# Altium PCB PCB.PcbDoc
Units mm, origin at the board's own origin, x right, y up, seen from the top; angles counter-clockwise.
Board outline 100 x 60 mm, 2 copper layers (Top Layer, Bottom Layer); 16 components, 14 nets, 66 pads, 0 vias.
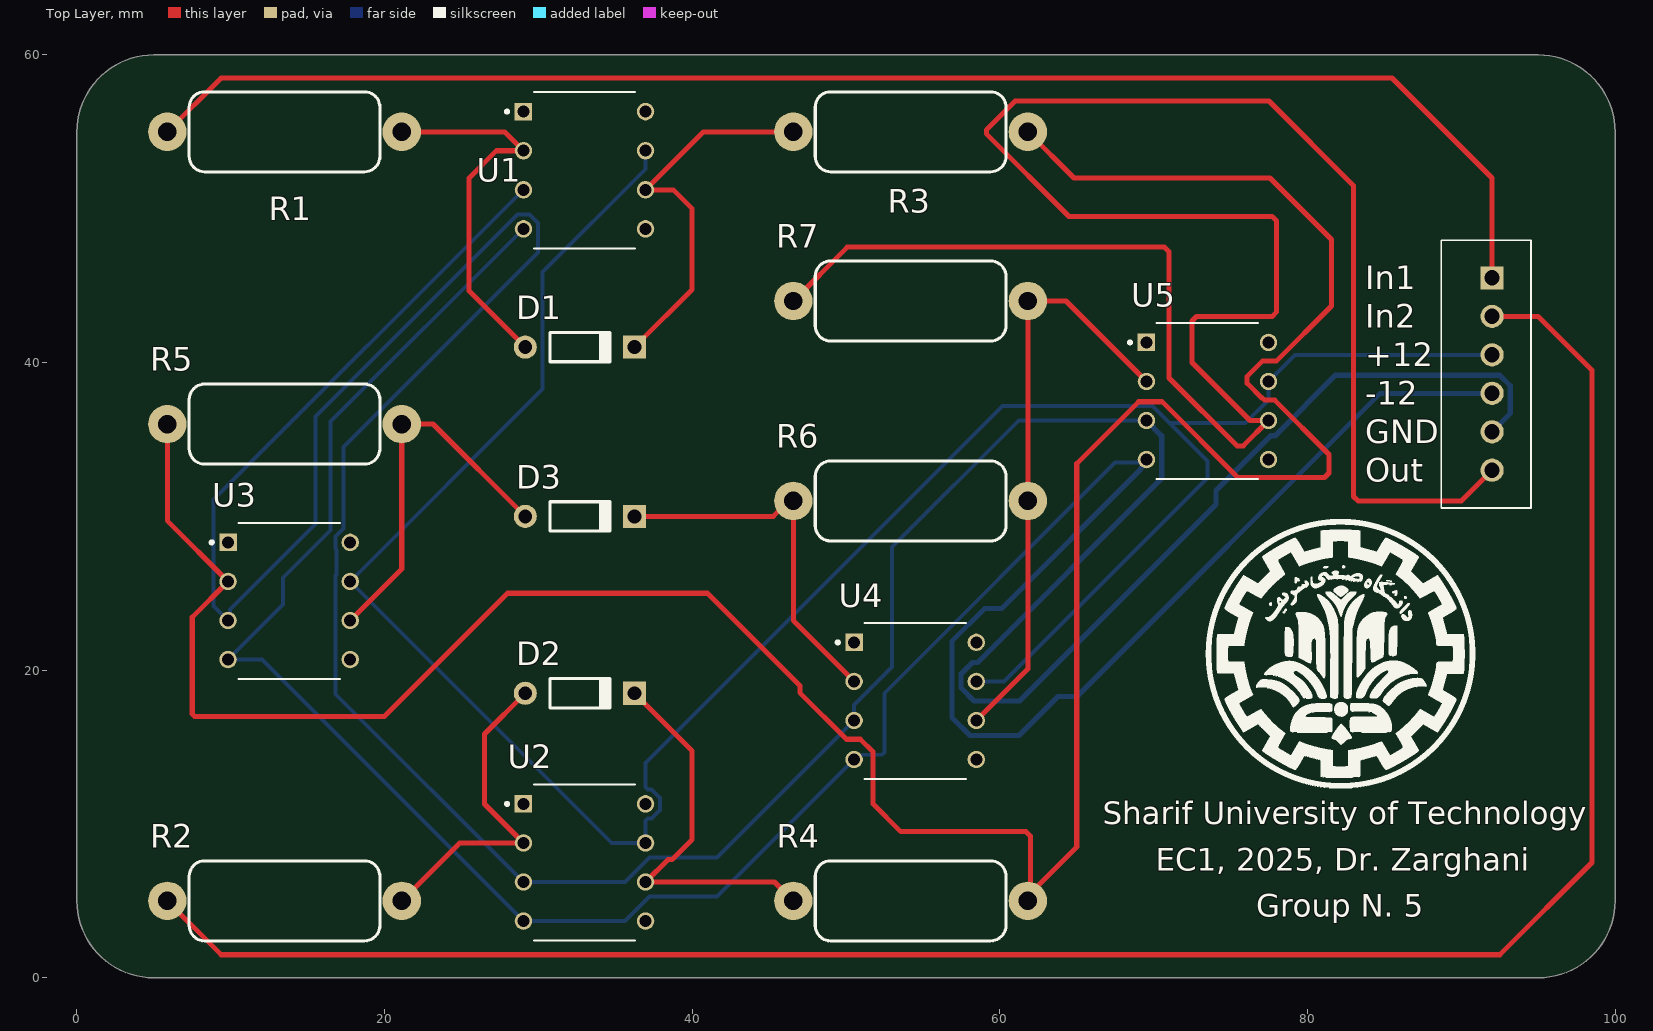
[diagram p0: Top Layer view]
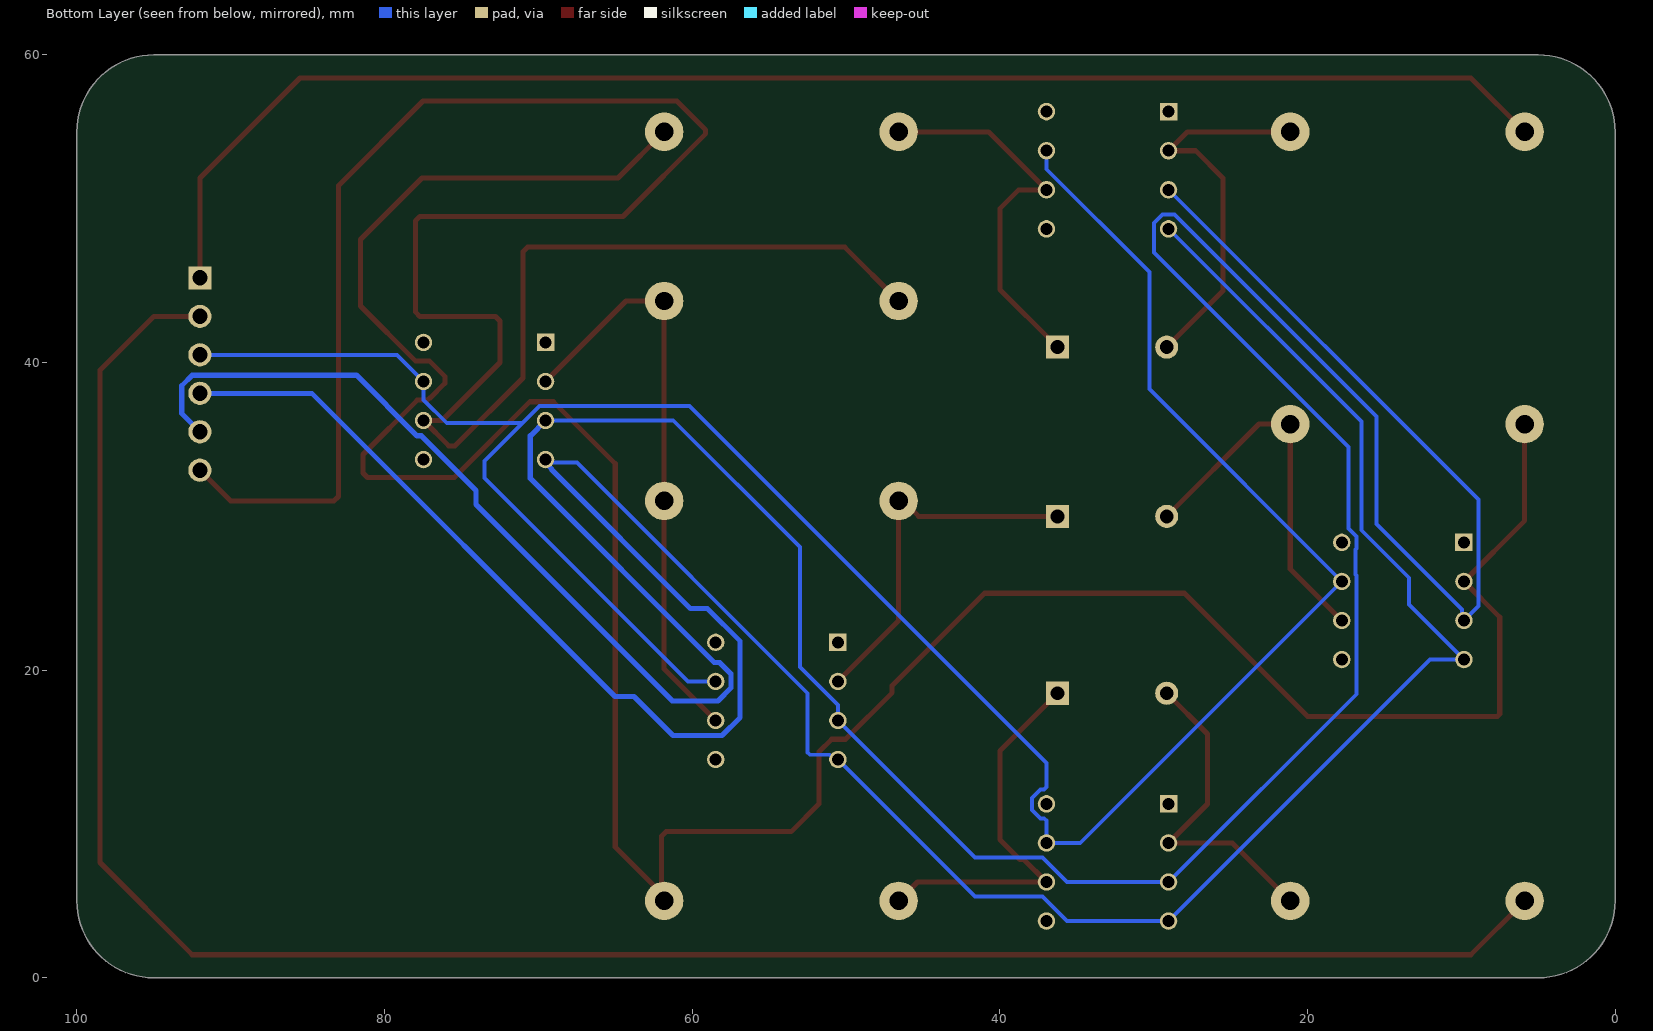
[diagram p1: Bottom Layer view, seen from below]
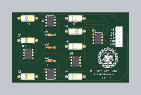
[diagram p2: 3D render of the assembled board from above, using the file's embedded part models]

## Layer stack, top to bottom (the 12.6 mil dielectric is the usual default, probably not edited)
Top Solder: solder mask 0.0102, Solder Resist, Dk 3.5
Top Layer: signal copper 0.0356
Dielectric 1: dielectric 0.32, FR-4, Dk 4.8
Bottom Layer: signal copper 0.0356
Bottom Solder: solder mask 0.0102, Solder Resist, Dk 3.5

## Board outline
0,5 0,55 cw(c5,55) 5,60 95,60 cw(c95,55) 100,55 100,5 cw(c95,5) 95,0 5,0 cw(c5,5)

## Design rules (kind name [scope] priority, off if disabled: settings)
Clearance Clearance_1 [All] p1: gap=0.254 ignorepadtopadclearanceinfootprint=FALSE
Clearance [All] p2: gap=0.254 ignorepadtopadclearanceinfootprint=FALSE
PolygonConnect [All] p1: connectstyle=Relief reliefconductorwidth=0.254 reliefentries=4 polygonreliefangle="90 Angle" airgapwidth=0.254
RoutingVias [All] p1: holewidth=0.711 width=1.27 viastyle="Through Hole" minholewidth=0.711 minwidth=1.27 maxholewidth=0.711 maxwidth=1.27
SolderMaskExpansion [All] p1: expansion=0.102 istentingtop=FALSE
SupplyNets "Schematic Supply Nets" [InNet('GND')] p1: voltage=0.000
Width [All] p1: maxlimit=0.35 minlimit=0.254 preferedwidth=0.3 minimp=50.000000 maximp=50.000000 favimp=50.000000
30 further rules are at their usual default settings.

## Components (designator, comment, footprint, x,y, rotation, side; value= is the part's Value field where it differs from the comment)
D1 "1N4148 THD" DO-35- 32.701,41 r0 top value=1N4148
D2 "1N4148 THD" DO-35- 32.701,18.5 r0 top value=1N4148
D3 "1N4148 THD" DO-35- 32.701,30 r0 top value=1N4148
"Pin Header" "XH 6" "XH 6 PIN" 91.365,39.424 r270 top
R1 "Resistor THD" R1W_AX06 13.5,55 r0 top value=1K
R2 "Resistor THD" R1W_AX06 13.5,5 r0 top value=1K
R3 "Resistor THD" R1W_AX06 54.201,55 r0 top value=1K
R4 "Resistor THD" R1W_AX06 54.201,5 r0 top value=1K
R5 "Resistor THD" R1W_AX06 13.5,36 r0 top value=1K
R6 "Resistor THD" R1W_AX06 54.201,31 r0 top value=1K
R7 "Resistor THD" R1W_AX06 54.201,44 r180 top value=1K
U1 "LM741CN/NOPB" DIP794W45P254L1016H508Q8 33,52.5 r0 top
U2 "LM741CN/NOPB" DIP794W45P254L1016H508Q8 33,7.5 r0 top
U3 "LM741CN/NOPB" DIP794W45P254L1016H508Q8 13.799,24.5 r0 top
U4 "LM741CN/NOPB" DIP794W45P254L1016H508Q8 54.5,18 r0 top
U5 "LM741CN/NOPB" DIP794W45P254L1016H508Q8 73.5,37.5 r0 top

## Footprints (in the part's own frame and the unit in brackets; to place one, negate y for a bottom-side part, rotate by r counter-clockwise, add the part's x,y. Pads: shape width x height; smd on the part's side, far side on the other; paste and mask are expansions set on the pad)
DIP794W45P254L1016H508Q8 [mm]
  rect 1.13x1.13 / inner round 1.13 / far side rect 1.13x1.13 hole 0.78: 1(-3.97,3.81)
  round 1.13 hole 0.78: 2(-3.97,1.27) 3(-3.97,-1.27) 4(-3.97,-3.81) 5(3.97,-3.81) 6(3.97,-1.27) 7(3.97,1.27) 8(3.97,3.81)
  silkscreen extent -5.13,-5.08 3.3,5.08, body extent -4.1,-4.79 4.1,4.79, height 5.08
DO-35- [mm] "Diode, Axial; Body 3.8 x 1.9 mm (LxDia. max), Lead Dia. 0.53 mm (max) (Make www.tarahiboard.com)"
  round 1.5 hole 0.9: 1(-3.55,0)
  rect 1.5x1.5 hole 0.9: 2(3.55,0)
  silkscreen extent -1.95,-0.95 2.05,0.95, body extent -3.82,-0.87 3.82,0.87, height 1.89
R1W_AX06 [mm] "RESISTOR 1 WATT, AXIAL0.6 (Make www.tarahiboard.com)"
  round 2.5 hole 1.2: 1(-7.62,0) 2(7.62,0)
  silkscreen extent -6.2,-2.6 6.2,2.6, body extent -7.97,-2.49 7.97,2.51, height 5
"XH 6 PIN" [mm] "(Make www.tarahiboard.com)"
  rect 1.508x1.508 hole 1: 1(-6.076,0.635)
  round 1.508 hole 1: 2(-3.576,0.635) 3(-1.076,0.635) 4(1.424,0.635) 5(3.924,0.635) 6(6.424,0.635)
  silkscreen extent -8.53,-2.67 8.89,3.18, body extent -8.51,-2.72 8.86,3.12, height 7.21

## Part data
D1 D2 D3: "High Conductance Fast Diode"
"Pin Header": library part "Conector XH 6 Pin", "Conector XH 6 Pin"
U1 U2 U3 U4 U5: "Ù…Ø¯Ø§Ø± ÛŒÚ©Ù¾Ø§Ø±Ú†Ù‡ Ø¢Ù…Ù¾Ø± Ø¹Ù…Ù„ÛŒØ§ØªÛŒ ØªÚ© Ù…Ù†Ø¸ÙˆØ±Ù‡ Ø¹Ù…ÙˆÙ…ÛŒ Ø´ÛŒØ¨ 8 Ø³Ø±Ø¨", Package="PDIP-8 Texas"

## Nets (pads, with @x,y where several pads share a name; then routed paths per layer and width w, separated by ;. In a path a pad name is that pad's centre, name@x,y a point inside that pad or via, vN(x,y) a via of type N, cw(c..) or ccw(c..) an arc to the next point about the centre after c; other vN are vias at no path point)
GND: "Pin Header.5" U1.3 U2.3 U3.3 U4.3 U5.3 | length 257.1
  Bottom Layer w0.254: U1.3 29.03,51.47 29,51.5 29,51.2 8.883,31.083 8.883,24.176 U3.3 9.945,23.345 9.945,23.945 15.5,29.5 15.5,36.498 28.638,49.636 29.422,49.636 29.976,49.082 29.976,47.163 17.331,34.518 17.331,29.21 16.823,28.702 16.823,27.918 16.879,27.863 16.879,26.217 16.823,26.162 16.823,18.437 U2.3 35.632,6.23 37.226,7.824 41.624,7.824 U4.3 50.53,17.748 53,20.218 53,28 61.23,36.23 U5.3
  Bottom Layer w0.35: U5.3 70.524,35.236 70.524,32.458 58.566,20.5 58.214,20.5 57.476,19.762 57.476,18.858 58.334,18 61.286,18 74.056,30.77 74.056,31.682 77.61,35.236 77.882,35.236 81.829,39.183 92.49,39.183 93.183,38.49 93.183,36.683 92,35.5
NetD1_1: D1.1 R1.2 U1.2 | length 25.3
  Top Layer w0.33: R1.2 27.8,55 U1.2 27.27,53.77 25.5,52 25.5,44.651 29,41.151 29,41 D1.1
NetD1_2: D1.2 R3.1 U1.6 | length 25.4
  Top Layer w0.33: D1.2 36.5,41 36.5,41.249 40,44.749 40,50 38.77,51.23 U1.6 40.74,55 R3.1
NetD2_1: D2.1 R2.2 U2.2 | length 21.3
  Top Layer w0.33: R2.2 24.89,8.77 U2.2 26.5,11.3 26.5,15.849 D2.1
NetD2_2: D2.2 R4.1 U2.6 | length 25.5
  Top Layer w0.33: D2.2 36.5,18.5 36.5,18.251 40,14.751 40,9 38.699,7.699 38.439,7.699 U2.6 45.351,6.23 R4.1
NetD3_1: D3.1 R5.2 U3.6 | length 24.7
  Top Layer w0.33: U3.6 21.12,26.581 R5.2 23.151,36 D3.1
NetD3_2: D3.2 R6.1 U4.2 | length 24.1
  Top Layer w0.33: D3.2 45.274,30 46.274,31 R6.1 46.581,23.219 U4.2
"NetPin Header_1": "Pin Header.1" R1.1 | length 96.8
  Top Layer w0.33: R1.1 9.38,58.5 85.5,58.5 92,52 92,45.5
"NetPin Header_2": "Pin Header.2" R2.1 | length 136.5
  Top Layer w0.33: R2.1 9.38,1.5 92.5,1.5 98.5,7.5 98.5,39.5 95,43 92,43
"NetPin Header_3": "Pin Header.3" U1.7 U2.7 U3.7 U4.7 U5.7 | length 161.2
  Bottom Layer w0.254: U1.7 36.97,53.53 37,53.5 36.97,53.47 36.97,52.568 30.282,45.88 30.282,38.283 U3.7 34.769,8.77 U2.7 36.97,10.215 37.119,10.364 37.362,10.364 37.916,10.918 37.916,11.702 37.362,12.256 37.119,12.256 36.97,12.405 36.97,13.97 60.176,37.176 69.922,37.176 71.042,36.056 ; U4.7 60.27,19.27 73.5,32.5 73.5,33.598 71.042,36.056 ; 92,40.5 79.2,40.5 U5.7 77.47,37.568 75.958,36.056 71.042,36.056
"NetPin Header_4": "Pin Header.4" U1.4 U2.4 U3.4 U4.4 U5.4 | length 184.9
  Bottom Layer w0.254: U1.4 29.03,48.53 29,48.5 28.84,48.5 16.5,36.16 16.5,29.097 13.41,26.007 13.41,24.271 U3.4 12.03,20.69 U2.4 35.632,3.69 37.226,5.284 41.624,5.284 U4.4 50.767,14.19 51.077,14.5 52.351,14.5 52.5,14.649 52.5,18.5 67.5,33.5 69.5,33.5 U5.4@69.53,33.53
  Bottom Layer w0.33: U5.4 69.53,33.474 69.149,33.092 69.149,33.039 60.11,24 59,24 56.882,21.882 56.882,16.926 58.062,15.746 61.246,15.746 63.786,18.286 65.015,18.286 84.729,38 92,38
"NetPin Header_6": "Pin Header.6" R7.2 U5.6 | length 142.6
  Top Layer w0.33: R7.2 50.081,47.5 70.707,47.5 71,47.207 71,39 75.413,34.587 75.827,34.587 U5.6 76.27,36.23 72.5,40 72.5,42.707 72.793,43 77.707,43 78,43.293 78,49.207 77.707,49.5 64.5,49.5 59.124,54.876 59.124,55.124 61,57 77.5,57 83,51.5 83,31.293 83.293,31 90,31 92,33
NetR3_2: R3.2 R4.2 R5.1 U3.2 | length 185
  Top Layer w0.33: R5.1 5.88,29.719 U3.2 7.5,23.441 7.5,17.149 7.649,17 20,17 28,25 41,25 47,19 47,18.536 50.025,15.511 50.933,15.511 51.749,14.695 51.749,11.317 53.566,9.5 61.707,9.5 62,9.207 R4.2@62,5.5 ; R4.2 62,5.179 R4.2@62,5.5 ; R3.2 64.821,52 77.56,52 81.562,47.998 81.562,43.678 77.975,40.091 77.067,40.091 76.078,39.102 76.078,38.65 77.027,37.701 77.065,37.701 77.215,37.551 77.873,37.551 81.4,34.024 81.4,32.825 81.107,32.532 75.468,32.532 70.551,37.449 69.025,37.449 65,33.424 65,8.5 R4.2@62,5.5
NetR6_2: R6.2 R7.1 U4.6 U5.2 | length 38.8
  Top Layer w0.33: U4.6 61.821,20.081 R6.2 62,31 61.821,31.179 R7.1 64.3,44 U5.2
pads on no net: U1.1 U1.5 U1.8 U2.1 U2.5 U2.8 U3.1 U3.5 U3.8 U4.1 U4.5 U4.8 U5.1 U5.5 U5.8
copper on no net: | length 0.3
  Top Layer w0.33: 85.5,1199 85.675,1198.825 85.745,1198.825

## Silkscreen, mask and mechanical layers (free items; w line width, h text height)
Top Overlay:
  drawing of 33 lines, arcs and shapes, not listed
  text "In1" at 83.754,44.754 h1.52
  text "In2" at 83.754,42.254 h1.52
  text "+12" at 83.754,39.754 h1.52
  text "-12" at 83.754,37.254 h1.52
  text "GND" at 83.754,34.754 h1.52
  text "Out" at 83.754,32.254 h1.52
  text "Sharif University of Technology" at 66.678,9.488 h2.5
  text "EC1, 2025, Dr. Zarghani" at 70.121,6.488 h2.5
  text "Group N. 5" at 76.668,3.484 h2.5
Mechanical 1:
  the board outline again, w0.254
